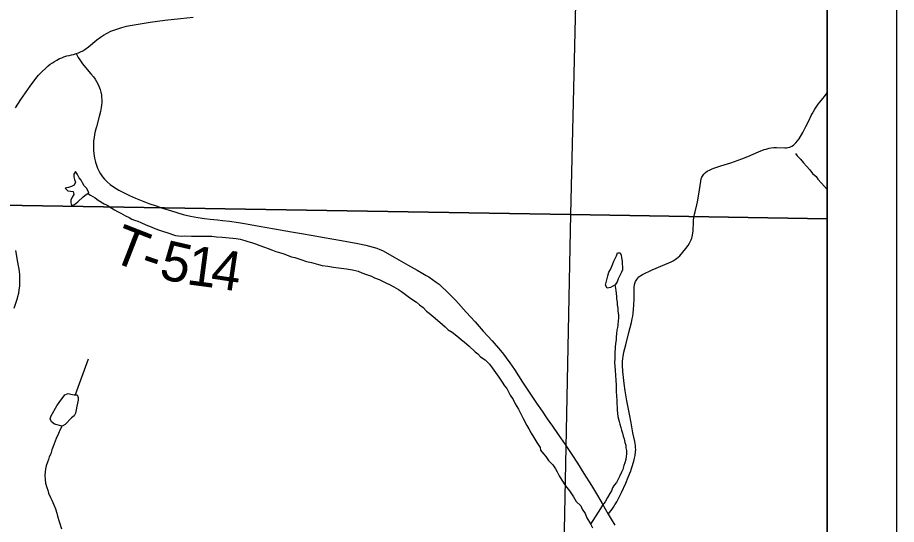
# Model space of a CAD drawing. Extents: x 0 to 34, y 0 to 22.
# Drawn here: x 29.148 to 30.417, y 19.094 to 19.826 of the extents above; entities that cross this region are included whole.
import ezdxf

# ---------------------------------------------------------------- set-up
doc = ezdxf.new("R2010")
doc.units = 0
for name, color, linetype in [('GM_X_Corporation', 7, 'Continuous'), ('GM_X_County_Road', 7, 'Continuous'), ('GM_X_Minor_River', 7, 'Continuous'), ('GM_X_Township_Road', 7, 'Continuous'), ('GM_X_Township_Road_Text', 7, 'Continuous'), ('SH_Data', 7, 'Continuous')]:
    doc.layers.add(name, color=color, linetype=linetype)

msp = doc.modelspace()

# ---------------------------------------------------------------- linework, layer by layer
at = {"layer": 'GM_X_Corporation'}
for points in [[(27.8031, 14.5091), (28.4032, 14.497), (28.7853, 14.4893), (29.1713, 14.4832), (29.2367, 14.4822), (30.3098, 14.464), (30.3167, 14.4639), (30.3167, 20.9), (27.1022, 20.9)], [(27.8031, 14.5091), (28.4032, 14.497), (28.7853, 14.4893), (29.1713, 14.4832), (29.2367, 14.4822), (30.3098, 14.464), (30.3167, 14.4639), (30.3167, 20.3649), (29.5503, 20.3788), (27.6751, 20.4106)]]:
    msp.add_lwpolyline(points, dxfattribs=at)
for points in [[(29.9657, 20.3723), (29.946, 19.5413), (28.9198, 19.5578), (28.9396, 20.3907)], [(30.3167, 19.535), (30.3167, 20.3654), (29.9657, 20.3723), (29.946, 19.5413)], [(28.9198, 19.5578), (29.946, 19.5413), (29.9261, 18.5329), (28.8973, 18.5532)], [(30.3167, 18.5238), (30.3167, 19.535), (29.946, 19.5413), (29.9261, 18.5329)]]:
    msp.add_lwpolyline(points, close=True, dxfattribs=at)
at = {"layer": 'GM_X_County_Road'}
for points in [[(29.1451, 19.6954), (29.1529, 19.7074), (29.1662, 19.7265), (29.173, 19.7358), (29.1763, 19.7398), (29.1783, 19.7422), (29.1835, 19.7477), (29.1883, 19.7522), (29.1924, 19.7558), (29.1953, 19.758), (29.1983, 19.7603), (29.2012, 19.7622), (29.2046, 19.7642), (29.2086, 19.7662), (29.2117, 19.7676), (29.2148, 19.7687), (29.2191, 19.7701), (29.2223, 19.7708), (29.2257, 19.7715), (29.2288, 19.7723), (29.2325, 19.7736), (29.2359, 19.7748), (29.2387, 19.7759), (29.2421, 19.7776), (29.2453, 19.7795), (29.2506, 19.7835), (29.2625, 19.7936), (29.2675, 19.7972), (29.2719, 19.8002), (29.2773, 19.8032), (29.2826, 19.8057), (29.2853, 19.8068), (29.2914, 19.809), (29.2984, 19.8112), (29.3052, 19.8129), (29.3136, 19.8147), (29.3249, 19.8167), (29.3393, 19.8189), (29.3604, 19.8217), (29.3833, 19.8242), (29.4016, 19.8262)], [(29.1433, 19.4059), (29.148, 19.4205), (29.1486, 19.4226), (29.1497, 19.4275), (29.1504, 19.4318), (29.1511, 19.4381), (29.1514, 19.4428), (29.1514, 19.448), (29.1512, 19.4534), (29.1506, 19.4591), (29.1486, 19.4725), (29.1455, 19.4893)]]:
    msp.add_lwpolyline(points, dxfattribs=at)
at = {"layer": 'GM_X_Minor_River'}
for points in [[(30.2709, 19.6294), (30.2732, 19.6257), (30.2782, 19.6208), (30.2825, 19.6156), (30.2871, 19.6107), (30.2917, 19.6055), (30.2956, 19.6002), (30.3006, 19.5962), (30.3033, 19.592), (30.3087, 19.5864), (30.313, 19.5816), (30.3167, 19.5773)], [(29.251, 19.5725), (29.2478, 19.5785), (29.244, 19.5826), (29.2416, 19.5868), (29.2397, 19.5905), (29.2369, 19.5943), (29.2346, 19.5988), (29.2315, 19.6033), (29.2293, 19.5995), (29.2294, 19.5953), (29.2302, 19.5915), (29.2314, 19.5877), (29.2296, 19.5835), (29.2258, 19.5816), (29.2213, 19.5803), (29.2168, 19.5791), (29.2206, 19.5754), (29.2244, 19.5747), (29.2282, 19.5744), (29.2291, 19.5699), (29.2269, 19.566), (29.225, 19.5618), (29.2247, 19.558), (29.2259, 19.5543), (29.2301, 19.5558), (29.2349, 19.5593), (29.2427, 19.5667), (29.2472, 19.5698), (29.251, 19.5725)], [(29.2495, 19.5714), (29.2533, 19.5692), (29.2598, 19.5651), (29.2644, 19.5618), (29.2728, 19.5566), (29.2774, 19.5544), (29.2843, 19.5504), (29.2881, 19.5481), (29.2923, 19.5456), (29.2969, 19.543), (29.3038, 19.5393), (29.3091, 19.5368), (29.3129, 19.5342), (29.3167, 19.5327), (29.3217, 19.5313), (29.3259, 19.5295), (29.3331, 19.5262), (29.3411, 19.5233), (29.3461, 19.5211), (29.3529, 19.5186), (29.3586, 19.5168), (29.3636, 19.5153), (29.3762, 19.511), (29.3803, 19.5103), (29.3853, 19.51), (29.3894, 19.5101), (29.3993, 19.5099), (29.4061, 19.5097), (29.4197, 19.5099), (29.4284, 19.5097), (29.4352, 19.509), (29.4432, 19.5084), (29.4485, 19.5077), (29.4636, 19.5065), (29.4693, 19.5055), (29.4762, 19.5037), (29.4804, 19.5022), (29.4857, 19.5008), (29.4914, 19.4986), (29.4975, 19.4965), (29.5044, 19.4939), (29.5097, 19.4918), (29.5158, 19.4896), (29.5207, 19.4878), (29.5245, 19.4867), (29.5325, 19.4842), (29.5436, 19.4802), (29.5481, 19.4788), (29.5569, 19.4763), (29.5653, 19.4734), (29.5721, 19.4716), (29.5824, 19.4688), (29.5877, 19.4674), (29.596, 19.4664), (29.604, 19.465), (29.6112, 19.464), (29.6226, 19.4627), (29.6313, 19.4613), (29.6397, 19.4592), (29.645, 19.457), (29.6519, 19.4545), (29.6591, 19.4519), (29.6633, 19.4497), (29.6698, 19.4472), (29.6759, 19.4443), (29.6797, 19.4424), (29.685, 19.4399), (29.6912, 19.4366), (29.698, 19.4329), (29.7023, 19.4299), (29.708, 19.4255), (29.7138, 19.4214), (29.7187, 19.4181), (29.7237, 19.4144), (29.7283, 19.4107), (29.7333, 19.4066), (29.7383, 19.4017), (29.7422, 19.3988), (29.7479, 19.3936), (29.7541, 19.3884), (29.7614, 19.3824), (29.7652, 19.3791), (29.7698, 19.3746), (29.7752, 19.3713), (29.7798, 19.3676), (29.7848, 19.3635), (29.789, 19.3601), (29.7928, 19.3572), (29.8001, 19.3512), (29.8086, 19.343), (29.8124, 19.3397), (29.8163, 19.3356), (29.8228, 19.3312), (29.8294, 19.3248), (29.8329, 19.3196), (29.8429, 19.3061), (29.8476, 19.299), (29.8511, 19.2937), (29.8542, 19.2896), (29.8565, 19.2851), (29.8593, 19.2802)], [(30.0109, 19.4396), (30.0037, 19.4357), (29.9992, 19.4345), (29.9969, 19.439), (30, 19.4527), (30.0015, 19.4576), (30.0037, 19.4615), (30.0055, 19.4653), (30.0073, 19.4699), (30.0087, 19.4737), (30.0124, 19.4814), (30.0142, 19.4856), (30.018, 19.486), (30.0192, 19.4822), (30.02, 19.4785), (30.0208, 19.4739), (30.0211, 19.4614), (30.02, 19.4576), (30.0152, 19.4484), (30.0134, 19.4438), (30.0109, 19.4396)], [(30.0101, 19.4392), (30.0105, 19.4373), (30.0114, 19.4313), (30.0122, 19.4271), (30.0127, 19.4229), (30.0127, 19.4191), (30.0136, 19.4146), (30.0136, 19.4108), (30.0145, 19.4059), (30.0145, 19.4017), (30.0154, 19.396), (30.0155, 19.3915), (30.0152, 19.3877), (30.0145, 19.3816), (30.0138, 19.3778), (30.0131, 19.374), (30.0128, 19.3694), (30.0122, 19.3641), (30.0119, 19.3599), (30.0112, 19.355), (30.0105, 19.3497), (30.01, 19.3406), (30.0101, 19.3333), (30.0098, 19.3269), (30.0103, 19.3227), (30.0108, 19.3151), (30.0113, 19.3098), (30.0114, 19.3007), (30.0119, 19.2958), (30.0121, 19.2856), (30.0126, 19.2787), (30.013, 19.2731), (30.0131, 19.2674), (30.0136, 19.2632), (30.0137, 19.2587), (30.0146, 19.2492), (30.0162, 19.2424), (30.0174, 19.2382), (30.019, 19.2337), (30.0199, 19.2296), (30.0214, 19.2254), (30.0223, 19.2212), (30.0235, 19.2171), (30.0247, 19.2118), (30.0259, 19.208), (30.026, 19.2039), (30.0268, 19.2001), (30.0269, 19.1955), (30.0266, 19.1917), (30.0259, 19.1875), (30.0245, 19.1826), (30.0234, 19.1784), (30.0216, 19.173), (30.0198, 19.1692), (30.0176, 19.1639), (30.0154, 19.16), (30.0125, 19.1543), (30.0091, 19.1501), (30.0069, 19.1462), (30.0055, 19.142), (30.0029, 19.1382), (29.9996, 19.1324), (29.9963, 19.1263), (29.9926, 19.1213), (29.9897, 19.1167), (29.9751, 19.0941)], [(29.2499, 19.3323), (29.2311, 19.2807)], [(29.2123, 19.2353), (29.2012, 19.2381), (29.197, 19.2415), (29.195, 19.246), (29.1965, 19.2502), (29.2049, 19.2648), (29.2082, 19.2694), (29.2104, 19.2732), (29.2138, 19.2771), (29.2164, 19.2809), (29.2209, 19.2825), (29.2251, 19.2818), (29.2296, 19.2808), (29.2342, 19.2805), (29.2354, 19.2767), (29.2354, 19.2729), (29.2347, 19.2687), (29.2337, 19.2641), (29.2326, 19.2588), (29.2316, 19.2542), (29.2298, 19.2504), (29.226, 19.2473), (29.2167, 19.2376), (29.2123, 19.2353)], [(29.8593, 19.2802), (29.8632, 19.2738), (29.8663, 19.2678), (29.871, 19.2599), (29.8741, 19.2543), (29.878, 19.2464), (29.8831, 19.2366), (29.8859, 19.2317), (29.8894, 19.2253), (29.8933, 19.219), (29.8976, 19.2118), (29.9022, 19.2047), (29.9031, 19.2009), (29.9073, 19.1957), (29.9104, 19.1916), (29.9143, 19.1859), (29.9205, 19.1796), (29.9243, 19.174), (29.9267, 19.1695), (29.9298, 19.1638), (29.9337, 19.1574), (29.9392, 19.1492), (29.9446, 19.1421), (29.9477, 19.1376), (29.9504, 19.1335), (29.9543, 19.1267), (29.9609, 19.1204), (29.9632, 19.1155), (29.9675, 19.1095), (29.9699, 19.1031), (29.9749, 19.0944), (29.9781, 19.0884)], [(29.2119, 19.2349), (29.2097, 19.2307), (29.2071, 19.225), (29.2035, 19.2177), (29.2024, 19.2139), (29.2006, 19.21), (29.1995, 19.2062), (29.1973, 19.2013), (29.1959, 19.1955), (29.1937, 19.1913), (29.1927, 19.1871), (29.1912, 19.1833), (29.1894, 19.178), (29.1884, 19.1738), (29.1877, 19.1696), (29.1874, 19.1643), (29.1879, 19.1582), (29.1883, 19.1529), (29.1903, 19.1469), (29.1919, 19.1431), (29.1928, 19.1386), (29.1955, 19.1326), (29.1975, 19.1284), (29.2002, 19.122), (29.2026, 19.116), (29.2046, 19.1096), (29.2058, 19.1054), (29.2082, 19.0979), (29.2115, 19.0873)]]:
    msp.add_lwpolyline(points, dxfattribs=at)
at = {"layer": 'GM_X_Township_Road'}
for points in [[(29.2325, 19.7736), (29.2357, 19.7681), (29.2378, 19.7643), (29.2418, 19.7585), (29.2459, 19.7536), (29.2539, 19.7443), (29.2574, 19.7398), (29.2598, 19.7364), (29.2619, 19.7333), (29.2639, 19.7297), (29.2653, 19.7264), (29.2672, 19.7215), (29.2681, 19.7179), (29.269, 19.7134), (29.2694, 19.7104), (29.2695, 19.7067), (29.2695, 19.7028), (29.2692, 19.6989), (29.2686, 19.6957), (29.2676, 19.6901), (29.2658, 19.6828), (29.2618, 19.6679), (29.2602, 19.6615), (29.2593, 19.6566), (29.2585, 19.6525), (29.2578, 19.6477), (29.2574, 19.6433), (29.2577, 19.6334), (29.2581, 19.6293), (29.2593, 19.6227), (29.2606, 19.6165), (29.2616, 19.6136), (29.2635, 19.608), (29.2656, 19.6033), (29.2677, 19.5997), (29.2706, 19.5955), (29.2735, 19.592), (29.2775, 19.5881), (29.2817, 19.5844), (29.2866, 19.5809), (29.2942, 19.5761), (29.2981, 19.5741), (29.3027, 19.5718), (29.3096, 19.5685), (29.3184, 19.5647), (29.3281, 19.5608), (29.3377, 19.5572), (29.3481, 19.5534), (29.3573, 19.5503), (29.3702, 19.5462), (29.3872, 19.5413), (29.3976, 19.5388), (29.4083, 19.5367), (29.418, 19.5352), (29.4259, 19.5344), (29.4366, 19.5332), (29.4438, 19.5325), (29.4541, 19.5313), (29.4668, 19.5296), (29.4786, 19.5277), (29.497, 19.5243), (29.5189, 19.5204), (29.5432, 19.5161), (29.5581, 19.5136), (29.5749, 19.5108), (29.5875, 19.5085), (29.6044, 19.5054), (29.6211, 19.5024), (29.6394, 19.4991), (29.6507, 19.4967), (29.6559, 19.4954), (29.6611, 19.494), (29.6665, 19.4923), (29.671, 19.4906), (29.6749, 19.4889), (29.6791, 19.4867), (29.6916, 19.4796), (29.7119, 19.468), (29.7248, 19.4606), (29.7332, 19.456), (29.7378, 19.4532), (29.7418, 19.4509), (29.7469, 19.4474), (29.7523, 19.4435), (29.7565, 19.4403), (29.7611, 19.4361), (29.7666, 19.4311), (29.772, 19.4258), (29.7807, 19.4167), (29.7957, 19.4), (29.8084, 19.3859), (29.8201, 19.3728), (29.8329, 19.3586), (29.8449, 19.3448), (29.8496, 19.3395), (29.8535, 19.3341), (29.8585, 19.3271), (29.8653, 19.3171), (29.8769, 19.2989), (29.8865, 19.2846), (29.8971, 19.2688), (29.9052, 19.257), (29.9126, 19.246), (29.9201, 19.2354), (29.9286, 19.2232), (29.9385, 19.209), (29.948, 19.1944), (29.9561, 19.1819), (29.9654, 19.1672), (29.9765, 19.1499), (29.9867, 19.1327), (29.9921, 19.1236), (30.0005, 19.1084), (30.0049, 19.1013), (30.01, 19.0926)], [(30.3028, 19.6991), (30.3039, 19.7007), (30.3061, 19.7035), (30.3106, 19.7088), (30.313, 19.7116), (30.3153, 19.715), (30.3163, 19.7168), (30.3167, 19.7176)], [(30.0005, 19.1084), (30.0046, 19.1133), (30.0064, 19.1156), (30.0084, 19.1185), (30.0104, 19.1219), (30.0129, 19.1262), (30.0198, 19.1398), (30.026, 19.1529), (30.0296, 19.1616), (30.0331, 19.171), (30.0347, 19.1758), (30.0375, 19.1851), (30.0385, 19.1893), (30.0394, 19.1931), (30.0402, 19.1983), (30.0403, 19.2017), (30.0402, 19.2044), (30.0398, 19.2076), (30.0389, 19.2131), (30.0362, 19.2258), (30.0336, 19.2401), (30.0313, 19.2526), (30.0277, 19.2719), (30.0253, 19.2866), (30.0238, 19.2969), (30.0226, 19.3058), (30.0217, 19.3144), (30.0212, 19.3234), (30.0213, 19.3286), (30.0216, 19.3333), (30.0221, 19.3361), (30.0233, 19.3423), (30.0259, 19.3528), (30.0305, 19.3707), (30.0342, 19.385), (30.0354, 19.3906), (30.036, 19.3943), (30.0365, 19.398), (30.0373, 19.4044), (30.0377, 19.4104), (30.038, 19.4198), (30.0381, 19.4366), (30.0384, 19.4392), (30.039, 19.4415), (30.0401, 19.4444), (30.0417, 19.4471), (30.0432, 19.4492), (30.0448, 19.4509), (30.0475, 19.4528), (30.0503, 19.4543), (30.0643, 19.461), (30.0881, 19.4711), (30.0913, 19.4726), (30.0944, 19.4743), (30.0971, 19.4761), (30.0993, 19.4777), (30.1038, 19.4814), (30.1085, 19.4867), (30.1129, 19.492), (30.116, 19.4962), (30.1182, 19.4998), (30.1206, 19.5047), (30.1214, 19.5068), (30.1219, 19.5089), (30.123, 19.5141), (30.1233, 19.5174), (30.1235, 19.5299), (30.1238, 19.5334), (30.1245, 19.5381), (30.1252, 19.5414), (30.126, 19.545), (30.1286, 19.5552), (30.1295, 19.5596), (30.1314, 19.5705), (30.1341, 19.5891), (30.135, 19.5925), (30.1359, 19.595), (30.1367, 19.5966), (30.1375, 19.5978), (30.1387, 19.5992), (30.1413, 19.6017), (30.1437, 19.6035), (30.1477, 19.6058), (30.1508, 19.6072), (30.1531, 19.6081), (30.1634, 19.6112), (30.1777, 19.6159), (30.1934, 19.6215), (30.2023, 19.6249), (30.2178, 19.6318), (30.2258, 19.6348), (30.2287, 19.6357), (30.2331, 19.6368), (30.2357, 19.6373), (30.2396, 19.6378), (30.2435, 19.638), (30.2555, 19.6373), (30.2581, 19.6375), (30.2597, 19.6378), (30.2628, 19.6386), (30.2658, 19.6399), (30.2681, 19.6412), (30.2717, 19.6445), (30.2741, 19.6473), (30.2763, 19.6504), (30.2817, 19.6595), (30.2859, 19.668), (30.2901, 19.6764), (30.2938, 19.6841), (30.2951, 19.6865), (30.299, 19.6934), (30.3017, 19.6976), (30.3028, 19.6991)]]:
    msp.add_lwpolyline(points, dxfattribs=at)
at = {"layer": 'SH_Data'}
for points in [[(23.4167, 21), (30.4167, 21), (30.4167, 14), (23.4167, 14)], [(23.5167, 20.9), (30.3167, 20.9), (30.3167, 14.1), (23.5167, 14.1)]]:
    msp.add_lwpolyline(points, close=True, dxfattribs=at)

# ---------------------------------------------------------------- texts
at = {"layer": 'GM_X_Township_Road_Text'}
for s, rotation, p in [('T', 338.7111, (29.2802, 19.4751)), ('5', 347.0167, (29.3505, 19.4495)), ('1', 352.5147, (29.3904, 19.4406)), ('4', 351.6175, (29.4249, 19.436)), ('-', 341.0913, (29.3223, 19.4588))]:
    msp.add_text(s, height=0.0568, rotation=rotation, dxfattribs=at).set_placement(p)

doc.saveas('drawing.dxf')
